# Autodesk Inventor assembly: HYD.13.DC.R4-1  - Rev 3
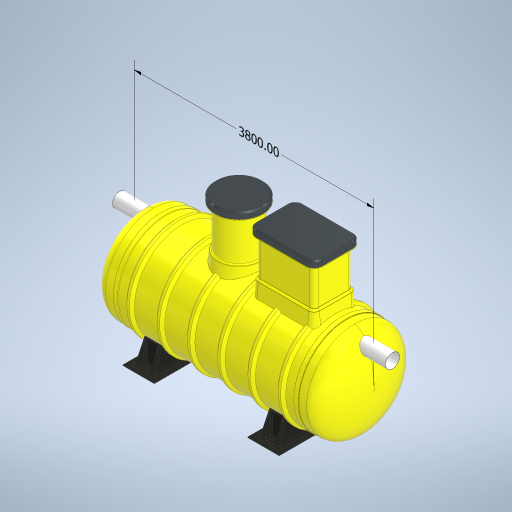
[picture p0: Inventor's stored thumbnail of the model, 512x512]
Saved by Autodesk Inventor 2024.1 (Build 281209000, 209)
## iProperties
Created: 2023-10
Part Number: HYD.13.DC.R4-1  - Rev 3
Document SubType Name: Assembly
Designer: macga
Author: macga
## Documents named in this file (42)
- D:\$ Protector Vault\Workspace\Automation Files\1. Protector Stardard Products\HydroProtectors\FAMILY\HYD.13 - Vernon\HYD.13.DC.R4-1  - Rev 3.iam
- D:\$ Protector Vault\Workspace\1. Protector Stardard Products\HydroProtectors\FAMILY\HORIZONTAL TANK - IPART\HORIZONTAL TANK - IPART.ipt
- D:\$ Protector Vault\Workspace\1. Protector Stardard Products\HydroProtectors\FAMILY\DOME - IPART\DOME - IPART\SU.DOME.1500-7.ipt
- D:\$ Protector Vault\Workspace\1. Protector Stardard Products\HydroProtectors\FAMILY\DOME - IPART\DOME - IPART.ipt
- D:\$ Protector Vault\Workspace\1. Protector Stardard Products\HydroProtectors\FAMILY\HYD.BAFFLE - IPART\SU.BAFFLE.1500\SU.BAFFLE.1500-300x225x175.ipt
- D:\$ Protector Vault\Workspace\1. Protector Stardard Products\HydroProtectors\FAMILY\HYD.BAFFLE - IPART\SU.BAFFLE.1500.ipt
- D:\$ Protector Vault\Workspace\1. Protector Stardard Products\HydroProtectors\FAMILY\ACD Base - IPART\SU.ACDBASE.1500\SU.ACDBASE.1500-190,300.ipt
- D:\$ Protector Vault\Workspace\1. Protector Stardard Products\HydroProtectors\FAMILY\ACD Base - IPART\SU.ACDBASE.1500.ipt
- D:\$ Protector Vault\Workspace\1. Protector Stardard Products\HydroProtectors\FAMILY\ACDTUBE - IPART\ACDTUBE - IPART.ipt
- D:\$ Protector Vault\Workspace\1. Protector Stardard Products\HydroProtectors\FAMILY\ACD FLOAT VALVE - IPART\ACD.FloatValve - IASSY\ACD.FVALVE.225.ASSY.iam
- D:\$ Protector Vault\Workspace\1. Protector Stardard Products\HydroProtectors\FAMILY\ACD FLOAT VALVE - IPART\ACD.FloatValve - IASSY.iam
- D:\$ Protector Vault\Workspace\1. Protector Stardard Products\HydroProtectors\FAMILY\ACDTUBE - IPART\ACDTUBE - IPART\ACDTUBE.225-1680.ipt
- D:\$ Protector Vault\Workspace\1. Protector Stardard Products\HydroProtectors\FAMILY\SU.600Dia Manway Adaptor - IPART\SU.MWA.HS.6R - IPART.ipt
- D:\$ Protector Vault\Workspace\1. Protector Stardard Products\HydroProtectors\FAMILY\SU.600Dia Manway Adaptor - IPART\Horizontal 600mmDia Manway Adaptor (FLANGED) SU.MWA.HS.6R-1850-1850\SU.MWA.HS.6R-1500.ipt
- D:\$ Protector Vault\Workspace\1. Protector Stardard Products\HydroProtectors\FAMILY\600x900mm Manway Adaptor - IPART\600x900mm Manway Adaptor - IPART\SU.MRADAPTOR.1500.600Lx900W.ipt
- D:\$ Protector Vault\Workspace\1. Protector Stardard Products\HydroProtectors\FAMILY\600x900mm Manway Adaptor - IPART\600x900mm Manway Adaptor - IPART.ipt
- D:\$ Protector Vault\Workspace\1. Protector Stardard Products\HydroProtectors\FAMILY\CF.BASE - IPART\CF BASE SINGLE - IPART\SU.CFBASE.1500\SU.CFBASE.1500.ipt
- D:\$ Protector Vault\Workspace\1. Protector Stardard Products\HydroProtectors\FAMILY\CF.BASE - IPART\CF BASE SINGLE - IPART\SU.CFBASE.1500.ipt
- D:\$ Protector Vault\Workspace\1. Protector Stardard Products\HydroProtectors\FAMILY\COALESCER FILTER - IPART\CF-R4.iam
- D:\$ Protector Vault\Workspace\1. Protector Stardard Products\HydroProtectors\Coalescer Guide Rail.ipt
- D:\$ Protector Vault\Workspace\1. Protector Stardard Products\Standard Components\600mm Riser.ipt
- D:\$ Protector Vault\Workspace\1. Protector Stardard Products\Standard Components\600x900 - 600mm Manway Riser.ipt
- D:\$ Protector Vault\Workspace\1. Protector Stardard Products\Standard Components\Flanged Vent.ipt
- D:\$ Protector Vault\Workspace\1. Protector Stardard Products\HydroProtectors\Upper Guide Rai Braket.ipt
- D:\$ Protector Vault\Workspace\Automation Files\1. Protector Stardard Products\HydroProtectors\FAMILY\CF.BASE - IPART\Moulds\Coalescer Guide Rail-0121.ipt
- D:\$ Protector Vault\Workspace\1. Protector Stardard Products\Xtremeprotector\Vault\Lifting Eye.ipt
- D:\$ Protector Vault\Workspace\1. Protector Stardard Products\Xtremeprotector\Vault\Chain.ipt
- D:\$ Protector Vault\Workspace\1. Protector Stardard Products\Xtremeprotector\Vault\Chain\Chain-29.ipt
- D:\$ Protector Vault\Workspace\1. Protector Stardard Products\Standard Components\600mm Cast Iron Cover ST\600mm Cass D Cover-01.ipt
- D:\$ Protector Vault\Workspace\1. Protector Stardard Products\Standard Components\600mm Cast Iron Cover ST.ipt
- D:\$ Protector Vault\Workspace\Automation Files\600x900mm Manway Cover ST B and D\600x900mm Manway Cover-D.ipt
- D:\$ Protector Vault\Workspace\Automation Files\600x900mm Manway Cover ST B and D.ipt
- D:\$ Protector Vault\Workspace\1. Protector Stardard Products\Horizontal Storage Tanks\ISO 4065 Pipe DN225x1.8xS63 - 1000.ipt
- D:\$ Protector Vault\Workspace\1. Protector Stardard Products\HydroProtectors\FAMILY\OUTLET ELBOW - IPART\OUTLET ELBOW - IPART.ipt
- D:\$ Protector Vault\Workspace\1. Protector Stardard Products\HydroProtectors\FAMILY\OUTLET ELBOW - IPART\OUTLET ELBOW - IPART\OutletPipeElbow.225D-100DCoupling.ipt
- D:\$ Protector Vault\Workspace\1. Protector Stardard Products\HydroProtectors\FAMILY\INLET PIPE ELBOW- IPART\INLET PIPE ELBOW- IPART\InletPipeElbow.225D.ipt
- D:\$ Protector Vault\Workspace\1. Protector Stardard Products\HydroProtectors\FAMILY\INLET PIPE ELBOW- IPART\INLET PIPE ELBOW- IPART.ipt
- D:\$ Protector Vault\Workspace\1. Protector Stardard Products\HydroProtectors\HYD Oil Probe\Oil Probe Assembly.iam
- D:\$ Protector Vault\Workspace\1. Protector Stardard Products\HydroProtectors\FAMILY\FOOT - IPART\FRP Foot - IPART\SU.HS.FOOT.1500.ipt
- D:\$ Protector Vault\Workspace\1. Protector Stardard Products\HydroProtectors\FAMILY\FOOT - IPART\FRP Foot - IPART.ipt
- D:\$ Protector Vault\Workspace\1. Protector Stardard Products\HydroProtectors\FAMILY\HORIZONTAL TANK - IPART\HORIZONTAL TANK - IPART\WIN.HB.1500x2920L-7.ipt
- D:\$ Protector Vault\Workspace\1. Protector Stardard Products\Trade Waste Sampling Point Assembly 225.iam
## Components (30 placed, 25 different names)
1. WIN.HB.1500x2920L-7:1
2. SU.DOME.1500-7:1 — Mate:3, Mate:4, Angle:7, Mate:6, Flush:1, Flush:56
3. SU.DOME.1500-7:2 — Mate:1, Mate:5, Angle:8
4. SU.BAFFLE.1500-300x225x175:1 — Mate:6, Angle:9, Flush:1, Mate:8, Mate:28, Mate:63
5. SU.ACDBASE.1500-190,300:1 — Mate:7, Mate:8, Angle:10, Mate:9, Mate:10
6. ACDTUBE.225-1680:1 — Mate:9, Mate:10, Angle:11, Mate:11, Flush:2, Mate:22
7. ACD.FVALVE.225.ASSY:1 [sub-assembly] — Mate:11, Flush:2
8. SU.CFBASE.1500:1
9. SU.MWA.HS.6R-1500:1 — Mate:22, Angle:13, Mate:23, Mate:33, Mate:34, Mate:35, Mate:58, Flush:57
10. SU.MRADAPTOR.1500.600Lx900W:1 — Mate:24, Mate:30, Mate:31, Mate:32, Mate:36, Mate:37
11. CF-R4:1 [sub-assembly] — Mate:25, Mate:26, Tangent:1, Tangent:2, Mate:43
12. Coalescer Guide Rail-0121:1 — Mate:27, Mate:28, Mate:29, Tangent:1, Mate:38, Mate:39, Flush:23
13. 600mm Riser:1 — Flush:22, Mate:33, Mate:44, Mate:45
14. 600x900 - 600mm Manway Riser:1
15. Flanged Vent:1 — Mate:34, Mate:35
16. Flanged Vent:2 — Mate:36, Mate:37
17. Upper Guide Rai Braket:1 — Mate:38, Mate:39, Flush:23
18. Lifting Eye:1 — Mate:40, Mate:41, Mate:42, Tangent:3
19. Chain-29:1 — Tangent:2, Mate:43, Tangent:3
20. 600mm Cass D Cover-01:1 — Mate:44, Mate:45
21. 600x900mm Manway Cover-D:1 — Mate:46, Flush:24, Flush:25
22. ISO 4065 Pipe DN225x1.8xS63 - 1000:1 — Mate:47, Mate:48, Mate:49, Mate:50
23. OutletPipeElbow.225D-100DCoupling:1 — Mate:49, Mate:50, Mate:51, Mate:52, Mate:53
24. ISO 4065 Pipe DN225x1.8xS63 - 1000:2 — Mate:52, Mate:53, Mate:54, Mate:64, Mate:65
25. ISO 4065 Pipe DN225x1.8xS63 - 1000:3 — Mate:54, Flush:56, Mate:56, Mate:57
26. InletPipeElbow.225D:1 — Mate:55, Mate:56, Mate:57
27. Oil Probe Assembly:1 [sub-assembly] — Mate:58, Flush:57, Angle:17
28. SU.HS.FOOT.1500:1 — Mate:59, Mate:60, Angle:15
29. SU.HS.FOOT.1500:2 — Mate:61, Mate:62, Angle:16
30. Trade Waste Sampling Point Assembly 225:1 [sub-assembly] — Mate:64, Mate:65
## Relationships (74: Mate 54, Angle 9, Flush 8, Tangent 3)
- Mate:1: SU.DOME.1500-7:2
- Mate:3: SU.DOME.1500-7:1
- Mate:4: SU.DOME.1500-7:1
- Mate:5: SU.DOME.1500-7:2
- Angle:7: SU.DOME.1500-7:1
- Angle:8: SU.DOME.1500-7:2
- Mate:6: SU.DOME.1500-7:1 ↔ SU.BAFFLE.1500-300x225x175:1
- Angle:9: SU.BAFFLE.1500-300x225x175:1
- Flush:1: SU.DOME.1500-7:1 ↔ SU.BAFFLE.1500-300x225x175:1
- Mate:7: SU.ACDBASE.1500-190,300:1
- Mate:8: SU.BAFFLE.1500-300x225x175:1 ↔ SU.ACDBASE.1500-190,300:1
- Angle:10: SU.ACDBASE.1500-190,300:1
- Mate:9: SU.ACDBASE.1500-190,300:1 ↔ ACDTUBE.225-1680:1
- Mate:10: SU.ACDBASE.1500-190,300:1 ↔ ACDTUBE.225-1680:1
- Angle:11: ACDTUBE.225-1680:1
- Mate:11: ACDTUBE.225-1680:1 ↔ ACD.FVALVE.225.ASSY:1
- Flush:2: ACDTUBE.225-1680:1 ↔ ACD.FVALVE.225.ASSY:1
- Mate:22: ACDTUBE.225-1680:1 ↔ SU.MWA.HS.6R-1500:1
- Angle:13: SU.MWA.HS.6R-1500:1
- Mate:23: SU.MWA.HS.6R-1500:1
- Mate:24: SU.MRADAPTOR.1500.600Lx900W:1
- Mate:25: CF-R4:1
- Mate:26: CF-R4:1
- Mate:27: Coalescer Guide Rail-0121:1
- Mate:28: SU.BAFFLE.1500-300x225x175:1 ↔ Coalescer Guide Rail-0121:1
- Mate:29: Coalescer Guide Rail-0121:1
- Tangent:1: CF-R4:1 ↔ Coalescer Guide Rail-0121:1
- Mate:30: SU.MRADAPTOR.1500.600Lx900W:1
- Mate:31: SU.MRADAPTOR.1500.600Lx900W:1
- Mate:32: SU.MRADAPTOR.1500.600Lx900W:1
- Flush:22: 600mm Riser:1
- Mate:33: SU.MWA.HS.6R-1500:1 ↔ 600mm Riser:1
- Mate:34: SU.MWA.HS.6R-1500:1 ↔ Flanged Vent:1
- Mate:35: SU.MWA.HS.6R-1500:1 ↔ Flanged Vent:1
- Mate:36: SU.MRADAPTOR.1500.600Lx900W:1 ↔ Flanged Vent:2
- Mate:37: SU.MRADAPTOR.1500.600Lx900W:1 ↔ Flanged Vent:2
- Mate:38: Coalescer Guide Rail-0121:1 ↔ Upper Guide Rai Braket:1
- Mate:39: Coalescer Guide Rail-0121:1 ↔ Upper Guide Rai Braket:1
- Flush:23: Coalescer Guide Rail-0121:1 ↔ Upper Guide Rai Braket:1
- Mate:40: Lifting Eye:1
- Mate:41: Lifting Eye:1
- Mate:42: Lifting Eye:1
- Tangent:2: CF-R4:1 ↔ Chain-29:1
- Mate:43: CF-R4:1 ↔ Chain-29:1
- Tangent:3: Lifting Eye:1 ↔ Chain-29:1
- Mate:44: 600mm Riser:1 ↔ 600mm Cass D Cover-01:1
- Mate:45: 600mm Riser:1 ↔ 600mm Cass D Cover-01:1
- Mate:46: 600x900mm Manway Cover-D:1
- Flush:24: 600x900mm Manway Cover-D:1
- Flush:25: 600x900mm Manway Cover-D:1
- Mate:47: ISO 4065 Pipe DN225x1.8xS63 - 1000:1
- Mate:48: ISO 4065 Pipe DN225x1.8xS63 - 1000:1
- Mate:49: ISO 4065 Pipe DN225x1.8xS63 - 1000:1 ↔ OutletPipeElbow.225D-100DCoupling:1
- Mate:50: ISO 4065 Pipe DN225x1.8xS63 - 1000:1 ↔ OutletPipeElbow.225D-100DCoupling:1
- Mate:51: OutletPipeElbow.225D-100DCoupling:1
- Mate:52: OutletPipeElbow.225D-100DCoupling:1 ↔ ISO 4065 Pipe DN225x1.8xS63 - 1000:2
- Mate:53: OutletPipeElbow.225D-100DCoupling:1 ↔ ISO 4065 Pipe DN225x1.8xS63 - 1000:2
- Mate:54: ISO 4065 Pipe DN225x1.8xS63 - 1000:2 ↔ ISO 4065 Pipe DN225x1.8xS63 - 1000:3
- Flush:56: SU.DOME.1500-7:1 ↔ ISO 4065 Pipe DN225x1.8xS63 - 1000:3
- Mate:55: InletPipeElbow.225D:1
- Mate:56: ISO 4065 Pipe DN225x1.8xS63 - 1000:3 ↔ InletPipeElbow.225D:1
- Mate:57: ISO 4065 Pipe DN225x1.8xS63 - 1000:3 ↔ InletPipeElbow.225D:1
- Mate:58: SU.MWA.HS.6R-1500:1 ↔ Oil Probe Assembly:1
- Flush:57: SU.MWA.HS.6R-1500:1 ↔ Oil Probe Assembly:1
- Mate:59: SU.HS.FOOT.1500:1
- Mate:60: SU.HS.FOOT.1500:1
- Mate:61: SU.HS.FOOT.1500:2
- Mate:62: SU.HS.FOOT.1500:2
- Angle:15: SU.HS.FOOT.1500:1
- Angle:16: SU.HS.FOOT.1500:2
- Mate:63: SU.BAFFLE.1500-300x225x175:1
- Angle:17: Oil Probe Assembly:1
- Mate:64: ISO 4065 Pipe DN225x1.8xS63 - 1000:2 ↔ Trade Waste Sampling Point Assembly 225:1
- Mate:65: ISO 4065 Pipe DN225x1.8xS63 - 1000:2 ↔ Trade Waste Sampling Point Assembly 225:1
